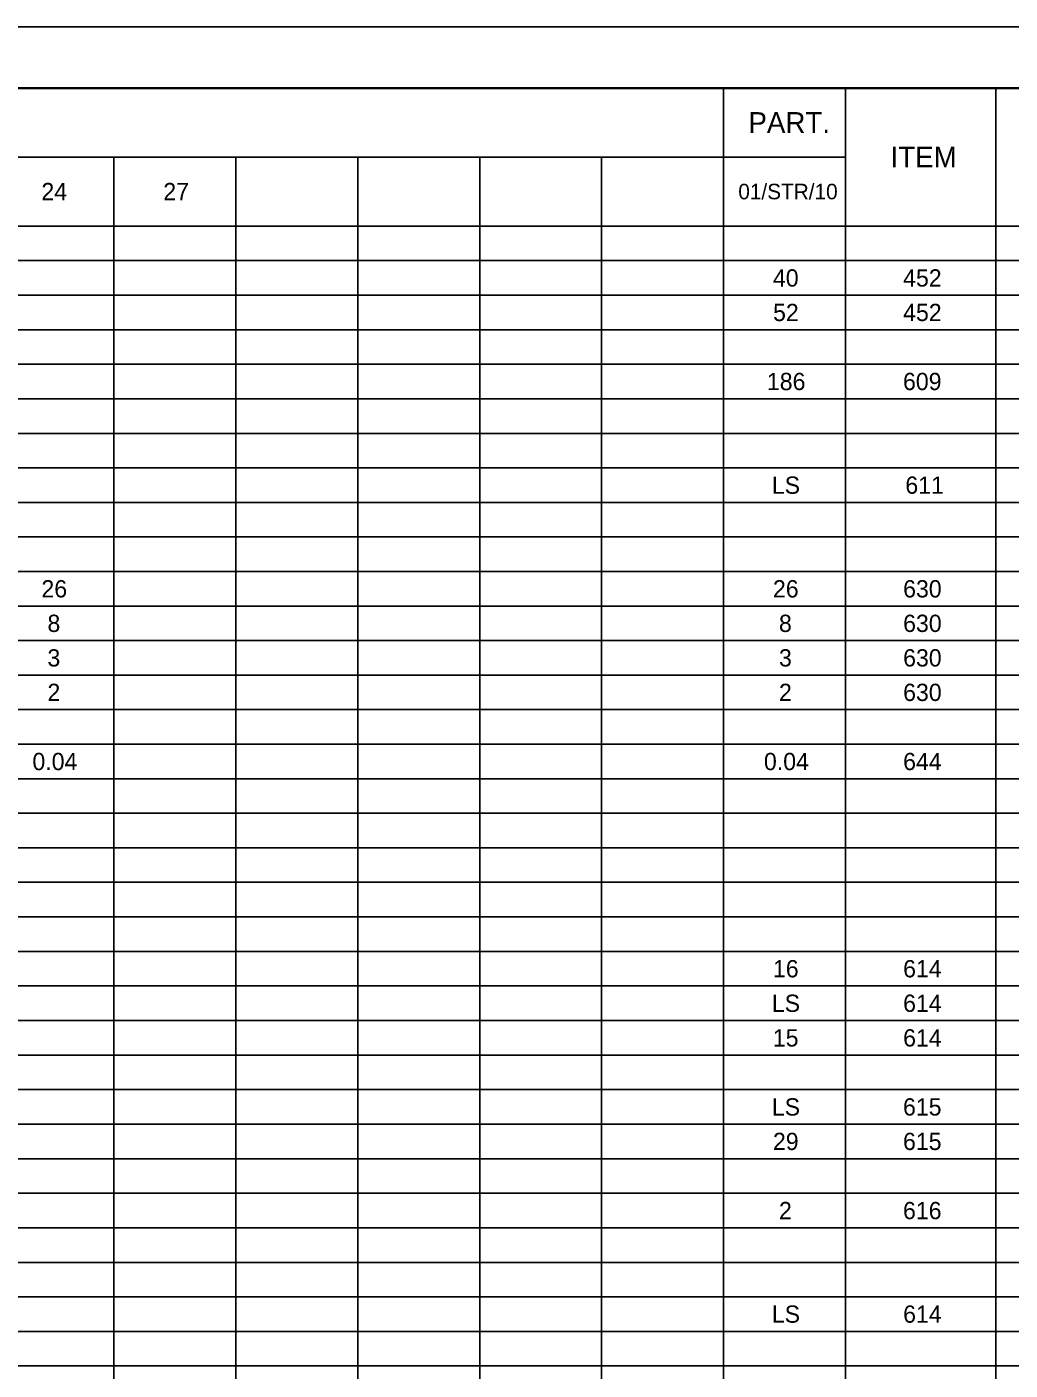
# Model space of a CAD drawing. Extents: x 0 to 34, y 0 to 22.
# Drawn here: x 8.71 to 16.69, y 11.1 to 22 of the extents above; entities that cross this region are included whole.
import ezdxf

# ---------------------------------------------------------------- set-up
doc = ezdxf.new("R2010")
doc.units = 0
for name, color, linetype in [('SH_Border', 7, 'Continuous'), ('SH_Cut_Line', 7, 'Continuous'), ('SH_Text', 7, 'Continuous')]:
    doc.layers.add(name, color=color, linetype=linetype)

msp = doc.modelspace()

# ---------------------------------------------------------------- linework, layer by layer
at = {"layer": 'SH_Border'}
msp.add_lwpolyline([(1.5, 21.5), (33.5, 21.5), (33.5, 0.5), (1.5, 0.5)], close=True, dxfattribs=at)
at = {"layer": 'SH_Cut_Line'}
msp.add_lwpolyline([(0, 0), (34, 0), (34, 22), (0, 22)], close=True, dxfattribs=at)
at = {"layer": 'SH_Text'}
for p, q in [((1.503, 21.505), (31.718, 21.505)), ((14.36, 21.505), (14.36, 0.488)), ((15.349, 21.505), (15.349, 0.488)), ((16.569, 21.505), (16.569, 0.488)), ((1.503, 20.944), (15.349, 20.944)), ((9.415, 20.944), (9.415, 0.488)), ((10.404, 20.944), (10.404, 0.488)), ((11.393, 20.944), (11.393, 0.488)), ((12.382, 20.944), (12.382, 0.488)), ((13.371, 20.944), (13.371, 0.488)), ((1.503, 20.384), (31.718, 20.384)), ((1.503, 20.104), (31.718, 20.104)), ((1.503, 19.823), (31.718, 19.823)), ((1.503, 19.543), (31.718, 19.543)), ((1.503, 19.263), (31.718, 19.263)), ((1.503, 18.983), (31.718, 18.983)), ((1.503, 18.702), (31.718, 18.702)), ((1.503, 18.422), (31.718, 18.422)), ((1.503, 18.142), (31.718, 18.142)), ((1.503, 17.862), (31.718, 17.862)), ((1.503, 17.582), (31.718, 17.582)), ((1.503, 17.301), (31.718, 17.301)), ((1.503, 17.021), (31.718, 17.021)), ((1.503, 16.741), (31.718, 16.741)), ((1.503, 16.461), (31.718, 16.461)), ((1.503, 16.18), (31.718, 16.18)), ((1.503, 15.9), (31.718, 15.9)), ((1.503, 15.62), (31.718, 15.62)), ((1.503, 15.34), (31.718, 15.34)), ((1.503, 15.06), (31.718, 15.06)), ((1.503, 14.779), (31.718, 14.779)), ((1.503, 14.499), (31.718, 14.499)), ((1.503, 14.219), (31.718, 14.219)), ((1.503, 13.939), (31.718, 13.939)), ((1.503, 13.658), (31.718, 13.658)), ((1.503, 13.378), (31.718, 13.378)), ((1.503, 13.098), (31.718, 13.098)), ((1.503, 12.818), (31.718, 12.818)), ((1.503, 12.538), (31.718, 12.538)), ((1.503, 12.257), (31.718, 12.257)), ((1.503, 11.977), (31.718, 11.977)), ((1.503, 11.697), (31.718, 11.697)), ((1.503, 11.417), (31.718, 11.417)), ((1.503, 11.136), (31.718, 11.136))]:
    msp.add_line(p, q, dxfattribs=at)

# ---------------------------------------------------------------- texts
for s, height, p in [('PART.', 0.1681, (14.562, 21.14)), ('ITEM', 0.1681, (15.715, 20.86)), ('24', 0.1401, (8.827, 20.594)), ('27', 0.1401, (9.816, 20.594)), ('01/STR/10', 0.1261, (14.48, 20.601)), ('40', 0.1401, (14.761, 19.893)), ('452', 0.1401, (15.817, 19.893)), ('52', 0.1401, (14.762, 19.613)), ('452', 0.1401, (15.817, 19.613)), ('186', 0.1401, (14.712, 19.053)), ('609', 0.1401, (15.816, 19.053)), ('LS', 0.1401, (14.752, 18.212)), ('611', 0.1401, (15.835, 18.212)), ('26', 0.1401, (8.827, 17.371)), ('26', 0.1401, (14.761, 17.371)), ('630', 0.1401, (15.817, 17.371)), ('8', 0.14, (8.876, 17.091)), ('8', 0.14, (14.81, 17.091)), ('630', 0.1401, (15.817, 17.091)), ('3', 0.14, (8.876, 16.811)), ('3', 0.14, (14.81, 16.811)), ('630', 0.1401, (15.817, 16.811)), ('2', 0.14, (8.876, 16.531)), ('2', 0.14, (14.81, 16.531)), ('630', 0.1401, (15.817, 16.531)), ('0.04', 0.1401, (8.754, 15.97)), ('0.04', 0.1401, (14.688, 15.97)), ('644', 0.1401, (15.817, 15.97)), ('16', 0.1401, (14.761, 14.289)), ('614', 0.1401, (15.817, 14.289)), ('LS', 0.1401, (14.752, 14.009)), ('614', 0.1401, (15.817, 14.009)), ('15', 0.1401, (14.76, 13.728)), ('614', 0.1401, (15.817, 13.728)), ('LS', 0.1401, (14.752, 13.168)), ('615', 0.1401, (15.816, 13.168)), ('29', 0.1401, (14.761, 12.888)), ('615', 0.1401, (15.816, 12.888)), ('2', 0.14, (14.81, 12.327)), ('616', 0.1401, (15.816, 12.327)), ('LS', 0.1401, (14.752, 11.487)), ('614', 0.1401, (15.817, 11.487))]:
    msp.add_text(s, height=height, dxfattribs=at).set_placement(p)

doc.saveas('drawing.dxf')
